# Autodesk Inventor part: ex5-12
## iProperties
Author: Administrator
Created: 2001-09
Part Number: ex5-12
Document SubType Name: Modeling
Designer: Administrator
Control State: 0
Master: False
Checked Out: False
PropertySet Name: Design Tracking Control
Length Units: 11272
Angle Units: 11279
Time Units: 11290
Mass Units: 11286
Shininess: 3
Angle Display Precision: 2
Document Length Units: 11272
Document Angle Units: 11286
Document Time Units: 11279
Document Mass Units: 11290
Document Length Units Precision: 3
Document Angle Units Precision: 2
Compacted: False
PropertySet Name: _Private Model Information
Density: 0.0
Volumn: 0.0
Area: 0.0
PropertySet Name: Model Information
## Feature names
1. Derived Body1 [Tagging]
